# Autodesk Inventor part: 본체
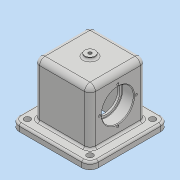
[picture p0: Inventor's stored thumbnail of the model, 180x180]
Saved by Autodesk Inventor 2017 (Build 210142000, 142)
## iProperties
Part Number: 본체
Material: 일반
Document SubType Name: Modeling
Designer: MRC
Density: 1 g/cm^3
Appearance: 기본값
Author: MRC
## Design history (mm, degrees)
sketch "스케치1"
  geometry: L1 (-58, 58)-(58, 58); L2 (58, 58)-(58, -58); L3 (58, -58)-(-58, -58); L4 (-58, -58)-(-58, 58); L5 (-58, 58)-(58, -58); L6 (58, 58)-(-58, -58); 1 further point
  constraints: 12 end point, 2 midpoint, 2 parallel, 1 horizontal, 1 perpendicular
  dimensions: "d0" = 116 distance of L2.end L3.end; "d1" = 116 distance of L1.end L2.end
extrude "돌출1" new body sketch "스케치1" distance "d2" = 10; taper "d3" = 0 deg
sketch "스케치2"
  geometry: L1 (-41, 41)-(41, 41); L2 (41, 41)-(41, -41); L3 (41, -41)-(-41, -41); L4 (-41, -41)-(-41, 41); L5 (-41, 41)-(41, -41); L6 (41, 41)-(-41, -41); 1 further point
  constraints: 12 end point, 2 midpoint, 2 parallel, 1 horizontal, 1 perpendicular
  dimensions: "d4" = 82 distance of L2.end L3.end; "d5" = 82 distance of L1.end L2.end
extrude "돌출2" join sketch "스케치2" distance "d6" = 80; taper "d7" = 0 deg
node "작업 평면1"
sketch "스케치3"
  geometry: C1 r 7.5 at (0, 0); 1 further point
  constraints: 1 centre point, 1 coincident
  dimensions: "d9" = 15 diameter of C1
extrude "돌출3" join sketch "스케치3" stored distance "d10" = 161.25; taper "d11" = 0 deg
sketch "스케치4"
  geometry: L1 (-10, -17)-(-10, 99) reference; C1 r 23.5 at (38, 41); 2 further points
  constraints: 1 centre point, 1 horizontal alignment, 1 midpoint
  dimensions: "d12" = 47 diameter of C1; "d13" = 48 distance from line of L1 C1.centre
extrude "돌출4" cut sketch "스케치4" distance "d14" = 17; taper "d15" = 0 deg
sketch "스케치5"
  geometry: L1 (-21, 30)-(21, 30); L2 (21, 30)-(21, -30); L3 (21, -30)-(-21, -30); L4 (-21, -30)-(-21, 30); L5 (58, 58)-(-58, 58) reference; 4 further points
  constraints: 8 end point, 3 midpoint, 2 parallel, 1 horizontal, 1 horizontal alignment, 1 perpendicular, 1 vertical alignment
  dimensions: "d16" = 42 distance of L2.end L3.end; "d17" = 60 distance of L1.end L2.end
extrude "돌출5" cut sketch "스케치5" distance "d18" = 80; taper "d19" = 0 deg
sketch "스케치6"
  geometry: L1 (-48, -58)-(-48, 58) reference; C1 r 20 at (0, 0); 2 further points
  constraints: 1 centre point, 1 horizontal alignment, 1 midpoint
  dimensions: "d20" = 40 diameter of C1; "d21" = 48 distance from line of L1 C1.centre
extrude "돌출6" cut sketch "스케치6" distance "d22" = 104.5; taper "d23" = 0 deg
sketch "스케치7"
  geometry: C1 r 20 at (-38, 41) reference; C2 r 23.5 at (-38, 41); 1 further point
  constraints: 1 centre point, 1 coincident
  dimensions: "d24" = 47 diameter of C2
extrude "돌출7" cut sketch "스케치7" distance "d25" = 17; taper "d26" = 0 deg
sketch "스케치8" dims "d27" = 54
  geometry: C1 r 20 at (-38, 41) reference; 3 further points
  constraints: 2 horizontal alignment, 1 coincident, 2 other
hole "구멍1" sketch "스케치8" at (-65, 41) diameter "d28" = 3.242; stored, may be unused: countersink angle "d32" = 90 deg, drill point angle "d34" = 118 deg; dims "d29" = 8, "d30" = 4, "d31" = 2, "d33" = 10
sketch "스케치9"
  geometry: 2 further points
  constraints: 1 coincident
hole "구멍2" sketch "스케치9" at (0, 0) diameter "d38" = 4.917; stored, may be unused: countersink angle "d42" = 90 deg, drill point angle "d44" = 118 deg; dims "d39" = 38.35, "d40" = 4, "d41" = 2, "d43" = 38.35
fillet "모깎기1" dims "d45" = 12
sketch "스케치10"
  geometry: C1 r 4.5 at (-46, 46); C2 r 4.5 at (46, 46); C3 r 4.5 at (-46, -46); C4 r 4.5 at (46, -46); A1 r 12 centre (-46, 46) between (-46, 58) and (-58, 46) reference; A2 r 12 centre (46, 46) between (58, 46) and (46, 58) reference; A3 r 12 centre (-46, -46) between (-58, -46) and (-46, -58) reference; A4 r 12 centre (46, -46) between (46, -58) and (58, -46) reference; 1 further point
  constraints: 4 centre point, 4 coincident
  dimensions: "d46" = 9 diameter of C1; "d47" = 9 diameter of C2; "d48" = 9 diameter of C3; "d49" = 9 diameter of C4
extrude "돌출8" cut sketch "스케치10" distance "d50" = 17; taper "d51" = 0 deg
fillet "모깎기2" dims "d52" = 8
fillet "모깎기3" dims "d53" = 8
fillet "모깎기4" dims "d54" = 3
fillet "모깎기5" dims "d55" = 3
chamfer "모따기1" distance "d56" = 1; stored, may be unused: second distance "d57" = 2, angle "d58" = 45 deg
fillet "모깎기6" dims "d59" = 0.6
fillet "모깎기7" dims "d60" = 3
sketch "스케치11"
  geometry: L1 (-13, 82)-(79, 82) reference; 3 further points
  constraints: 1 midpoint, 1 vertical alignment, 1 other
  dimensions: "d61" = 48 distance from line of L1 point (33, 34)
feature "엠보싱1" sketch "스케치11" dims "d0" = 116, "d1" = 116, "d62" = 0.5, "d63" = 0
fillet "모깎기8" dims "d64" = 3
node "솔리드1"
pattern_circular "원형 패턴1" dims angle "d36" = 360 deg
mirror "미러1"
other parameters: "d8" = 94
